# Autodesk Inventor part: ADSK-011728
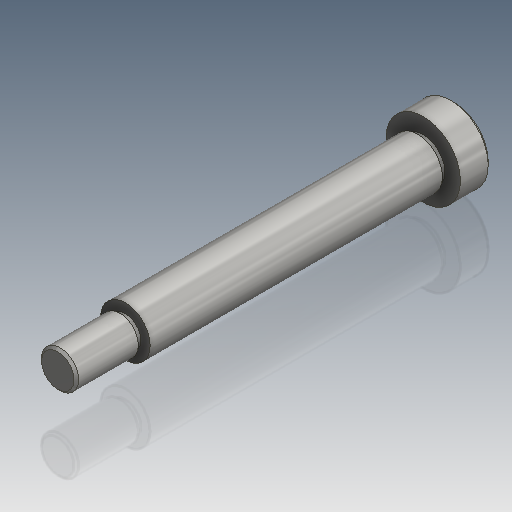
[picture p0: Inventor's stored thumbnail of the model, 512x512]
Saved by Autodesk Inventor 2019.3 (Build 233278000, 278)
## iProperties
Created: 1999-11
Part Number: ADSK-011728
Description: BOLT,SHOULDER,0.500X3.000
Document SubType Name: Modeling
Designer: mpflueger
Material: Pearson HRS
Density: 7.83 g/cm^3
Appearance: Steel
Mass: 100.44 g
Surface Area: 47.9038 cm^2
Volume: 12.8275 cm^3
Control State: 0
Master: False
Checked Out: False
Shininess: 25.0
Length Units: 11272
Angle Units: 11279
Time Units: 11290
Mass Units: 11286
Length Display Precision: 3
Angle Display Precision: 2
Compacted: True
Dimensions: 0,8x0,8x4 in
Mass: 0,221 lb
Density: 7.83
Volumn: 3.31456332564042
Area: 17.6158329786279
PropertySet Name: Model Information
Author: mpflueger
Revision Number: -
Title: BOLT,SHOULDER,0.500X3.000
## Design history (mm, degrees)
node "Extrusion1" dims "d2" = 0, "head_depth" = 8
  sketch "Sketch1"
    geometry: C1 r 10 at (0, 0); 1 further point
    constraints: 1 centre point, 1 coincident
    dimensions: "head_diameter" = 20 diameter of C1
node "Extrusion2" dims "d5" = 0, "Top_shoulder_gap" = 1.5
  sketch "Sketch2"
    geometry: C1 r 10 at (0, 0) reference; C2 r 5.456 at (0, 0)
    constraints: 1 centre point, 1 coincident
    dimensions: "Top_shoulder_gap_diameter" = 10.9125 diameter of C2 (computed from Shoulder_diameter)
node "Extrusion3" dims "d8" = 0, "Length" = 75
  sketch "Sketch3"
    geometry: C1 r 5.456 at (0, 0) reference; C2 r 6.25 at (0, 0)
    constraints: 1 centre point, 1 coincident
    dimensions: "Shoulder_diameter" = 12.5 diameter of C2
node "Extrusion4" dims "d11" = 0, "Bottom_shoulder_gap" = 1.5
  sketch "Sketch4"
    geometry: C1 r 6.25 at (0, 0) reference; C2 r 4 at (0, 0)
    constraints: 1 centre point, 1 coincident
    dimensions: "Bottom_shoulder_gap_diameter" = 8 diameter of C2
node "Extrusion5" dims "d14" = 0, "Thread_length" = 16
  sketch "Sketch5"
    geometry: C1 r 4 at (0, 0) reference; C2 r 5 at (0, 0)
    constraints: 1 centre point, 1 coincident
    dimensions: "Major_thread_diameter" = 10 diameter of C2
node "Chamfer1" dims "d15" = 0.5, "d16" = 0.5, "d21" = 45 deg
node "Chamfer2" dims "d17" = 1, "d18" = 1, "d22" = 45 deg
node "Hexagon_flats_cut1"
feature "Gewinde1" dims "d23" = 15.5, "d24" = 0
node "Solide1"
node "Corps solides"
node "Corps surfaciques"
sketch "Sketch6"
  geometry: L1 (-1.92, 2.669)-(0.278, 5.347); L2 (0.278, 5.347)-(3.696, 4.782); L3 (3.696, 4.782)-(4.916, 1.54); L4 (4.916, 1.54)-(2.718, -1.137); L5 (2.718, -1.137)-(-0.7, -0.573); L6 (-0.7, -0.573)-(-1.92, 2.669); C1 r 3 at (1.498, 2.105)
  constraints: 12 end point, 5 tangent, 3 equal length, 3 parallel, 1 centre point
  dimensions: "d19" = 6 diameter of C1 (derived)
other parameters: "Actual_barrel_length" = 73.5 (= Length - Top_shoulder_gap) [user parameter], "ATL" = 14.5 (= Thread_length - Bottom_shoulder_gap) [user parameter]
